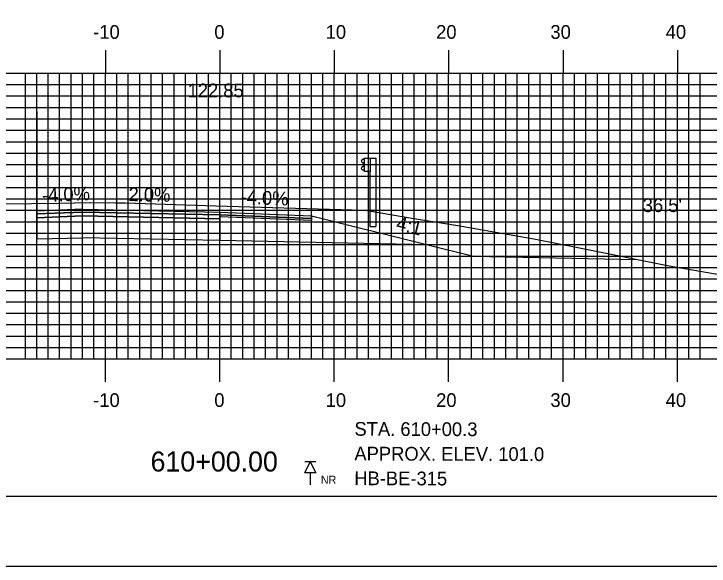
# Model space of a CAD drawing. Extents: x 843356 to 843699, y 363538 to 363758.
# Drawn here: x 843503.4 to 843564.2, y 363537.6 to 363585.9 of the extents above; entities that cross this region are included whole.
import ezdxf

# ---------------------------------------------------------------- set-up
doc = ezdxf.new("R2010")
doc.units = 0
for name, color, linetype in [('ANNOTATION', 7, 'Continuous'), ('BORDER', 7, 'Continuous'), ('BORING - NO REFUSAL', 7, 'Continuous'), ('D_Roadway_Centerline_Text', 7, 'Continuous'), ('D_Roadway_Edge_Shoulder', 7, 'Continuous'), ('D_Roadway_Edge_TW', 7, 'Continuous'), ('D_Roadway_FinishedGrade', 7, 'Continuous'), ('D_Roadway_Pavement', 7, 'Continuous'), ('D_Roadway_SubGrade', 7, 'Continuous'), ('D_Text_Standard', 7, 'Continuous'), ('H_V ANNOTATION', 7, 'Continuous'), ('M_Guardrail', 7, 'Continuous'), ('M_Roadway_Centerline', 7, 'Continuous'), ('MAJOR', 7, 'Continuous'), ('MINOR', 7, 'Continuous'), ('PLOT BOUNDARY', 7, 'Continuous'), ('S_Roadway_Centerline', 7, 'Continuous')]:
    doc.layers.add(name, color=color, linetype=linetype)

msp = doc.modelspace()

# ---------------------------------------------------------------- linework, layer by layer
at = {"layer": 'BORDER'}
msp.add_lwpolyline([(843371.824, 363543.721), (843691.824, 363543.721), (843691.824, 363753.721), (843371.824, 363753.721)], close=True, dxfattribs=at)
at = {"layer": 'BORING - NO REFUSAL'}
for p, q in [((843529.804, 363546.721), (843528.844, 363546.721)), ((843529.324, 363545.761), (843529.324, 363544.702))]:
    msp.add_line(p, q, dxfattribs=at)
msp.add_lwpolyline([(843529.324, 363546.721), (843529.804, 363545.761), (843528.844, 363545.761)], close=True, dxfattribs=at)
at = {"layer": 'D_Roadway_Edge_Shoulder'}
for points in [[(843509.424, 363568.812), (843505.424, 363568.652), (843505.424, 363568.402), (843509.424, 363568.562)], [(843521.424, 363568.572), (843529.424, 363568.252), (843529.424, 363568.002), (843521.424, 363568.322)]]:
    msp.add_lwpolyline(points, close=True, dxfattribs=at)
at = {"layer": 'D_Roadway_Edge_TW'}
msp.add_lwpolyline([(843509.424, 363568.812), (843521.424, 363568.572), (843521.424, 363568.322), (843509.424, 363568.562)], close=True, dxfattribs=at)
at = {"layer": 'D_Roadway_FinishedGrade'}
msp.add_lwpolyline([(843539.598, 363565.708), (843543.598, 363564.708), (843557.907, 363564.422)], dxfattribs=at)
at = {"layer": 'D_Roadway_Pavement'}
for points in [[(843509.424, 363568.562), (843505.424, 363568.402), (843505.424, 363568.068), (843509.424, 363568.228)], [(843509.424, 363568.562), (843521.424, 363568.322), (843521.424, 363567.988), (843509.424, 363568.228)], [(843521.424, 363568.322), (843529.424, 363568.002), (843529.424, 363567.835), (843521.424, 363568.155)]]:
    msp.add_lwpolyline(points, close=True, dxfattribs=at)
msp.add_lwpolyline([(843521.424, 363568.322), (843521.424, 363567.988)], dxfattribs=at)
msp.add_lwpolyline([(843521.424, 363568.322), (843521.424, 363567.988)], dxfattribs=at)
at = {"layer": 'D_Roadway_SubGrade'}
msp.add_line((843505.424, 363577.329), (843505.424, 363566.232), dxfattribs=at)
for points in [[(843509.424, 363568.228), (843505.424, 363568.068), (843505.424, 363568.402), (843505.424, 363568.652), (843505.424, 363566.232), (843509.424, 363566.312)], [(843509.424, 363568.228), (843521.424, 363567.988), (843521.424, 363566.072), (843509.424, 363566.312)], [(843521.424, 363567.988), (843521.424, 363568.322), (843529.424, 363568.002), (843529.424, 363568.252), (843539.598, 363565.708), (843521.424, 363566.072)]]:
    msp.add_lwpolyline(points, close=True, dxfattribs=at)
at = {"layer": 'M_Guardrail'}
for p, q in [((843534.069, 363573.291), (843534.559, 363573.291)), ((843534.069, 363572.125), (843534.069, 363573.291)), ((843534.559, 363573.291), (843535.05, 363573.291)), ((843534.559, 363573.291), (843534.559, 363572.125)), ((843535.05, 363573.291), (843535.05, 363567.291)), ((843533.971, 363573.197), (843533.827, 363573.097)), ((843533.827, 363572.954), (843534.022, 363572.818)), ((843534.069, 363573.218), (843533.987, 363573.204)), ((843534.056, 363572.753), (843534.056, 363572.662)), ((843534.022, 363572.598), (843533.827, 363572.462)), ((843533.827, 363572.319), (843533.971, 363572.219)), ((843533.987, 363572.212), (843534.069, 363572.197)), ((843534.559, 363572.125), (843534.069, 363572.125)), ((843534.559, 363567.291), (843534.559, 363572.125)), ((843534.559, 363567.291), (843535.05, 363567.291))]:
    msp.add_line(p, q, dxfattribs=at)
for centre, major_axis, start_param, end_param in [((843533.877, 363573.025), (-0.0877, 0), 5.323254, 7.243116), ((843533.994, 363573.163), (-0.0417, 0), 4.886922, 5.323254), ((843533.977, 363572.753), (0.0789, 0), 0, 0.959931), ((843533.977, 363572.662), (0.0789, 0), 5.323254, 6.283185), ((843533.877, 363572.39), (-0.0877, 0), 5.323254, 7.243116), ((843533.994, 363572.253), (-0.0417, 0), 0.959931, 1.396263)]:
    msp.add_ellipse(centre, major_axis=major_axis, ratio=0.995501, start_param=start_param, end_param=end_param, dxfattribs=at)
at = {"layer": 'MAJOR'}
for p, q in [((843511.424, 363582.725), (843511.424, 363580.721)), ((843521.424, 363582.725), (843521.424, 363580.721)), ((843531.424, 363582.725), (843531.424, 363580.721)), ((843541.424, 363582.725), (843541.424, 363580.721)), ((843551.424, 363582.725), (843551.424, 363580.721)), ((843561.424, 363582.725), (843561.424, 363580.721)), ((843381.424, 363580.721), (843661.424, 363580.721)), ((843381.424, 363580.721), (843661.424, 363580.721)), ((843511.424, 363555.721), (843511.424, 363580.721)), ((843521.424, 363555.721), (843521.424, 363580.721)), ((843531.424, 363555.721), (843531.424, 363580.721)), ((843541.424, 363555.721), (843541.424, 363580.721)), ((843551.424, 363555.721), (843551.424, 363580.721)), ((843561.424, 363555.721), (843561.424, 363580.721)), ((843381.424, 363575.721), (843661.424, 363575.721)), ((843381.424, 363570.721), (843661.424, 363570.721)), ((843381.424, 363565.721), (843661.424, 363565.721)), ((843381.424, 363560.721), (843661.424, 363560.721)), ((843381.424, 363555.721), (843661.424, 363555.721)), ((843381.424, 363555.721), (843661.424, 363555.721)), ((843511.424, 363553.717), (843511.424, 363555.721)), ((843521.424, 363553.717), (843521.424, 363555.721)), ((843531.424, 363553.717), (843531.424, 363555.721)), ((843541.424, 363553.717), (843541.424, 363555.721)), ((843551.424, 363553.717), (843551.424, 363555.721)), ((843561.424, 363553.717), (843561.424, 363555.721))]:
    msp.add_line(p, q, dxfattribs=at)
at = {"layer": 'MINOR'}
for p, q in [((843504.424, 363555.721), (843504.424, 363580.721)), ((843505.424, 363555.721), (843505.424, 363580.721)), ((843506.424, 363555.721), (843506.424, 363580.721)), ((843507.424, 363555.721), (843507.424, 363580.721)), ((843508.424, 363555.721), (843508.424, 363580.721)), ((843509.424, 363555.721), (843509.424, 363580.721)), ((843510.424, 363555.721), (843510.424, 363580.721)), ((843512.424, 363555.721), (843512.424, 363580.721)), ((843513.424, 363555.721), (843513.424, 363580.721)), ((843514.424, 363555.721), (843514.424, 363580.721)), ((843515.424, 363555.721), (843515.424, 363580.721)), ((843516.424, 363555.721), (843516.424, 363580.721)), ((843517.424, 363555.721), (843517.424, 363580.721)), ((843518.424, 363555.721), (843518.424, 363580.721)), ((843519.424, 363555.721), (843519.424, 363580.721)), ((843520.424, 363555.721), (843520.424, 363580.721)), ((843522.424, 363555.721), (843522.424, 363580.721)), ((843523.424, 363555.721), (843523.424, 363580.721)), ((843524.424, 363555.721), (843524.424, 363580.721)), ((843525.424, 363555.721), (843525.424, 363580.721)), ((843526.424, 363555.721), (843526.424, 363580.721)), ((843527.424, 363555.721), (843527.424, 363580.721)), ((843528.424, 363555.721), (843528.424, 363580.721)), ((843529.424, 363555.721), (843529.424, 363580.721)), ((843530.424, 363555.721), (843530.424, 363580.721)), ((843532.424, 363555.721), (843532.424, 363580.721)), ((843533.424, 363555.721), (843533.424, 363580.721)), ((843534.424, 363555.721), (843534.424, 363580.721)), ((843535.424, 363555.721), (843535.424, 363580.721)), ((843536.424, 363555.721), (843536.424, 363580.721)), ((843537.424, 363555.721), (843537.424, 363580.721)), ((843538.424, 363555.721), (843538.424, 363580.721)), ((843539.424, 363555.721), (843539.424, 363580.721)), ((843540.424, 363555.721), (843540.424, 363580.721)), ((843542.424, 363555.721), (843542.424, 363580.721)), ((843543.424, 363555.721), (843543.424, 363580.721)), ((843544.424, 363555.721), (843544.424, 363580.721)), ((843545.424, 363555.721), (843545.424, 363580.721)), ((843546.424, 363555.721), (843546.424, 363580.721)), ((843547.424, 363555.721), (843547.424, 363580.721)), ((843548.424, 363555.721), (843548.424, 363580.721)), ((843549.424, 363555.721), (843549.424, 363580.721)), ((843550.424, 363555.721), (843550.424, 363580.721)), ((843552.424, 363555.721), (843552.424, 363580.721)), ((843553.424, 363555.721), (843553.424, 363580.721)), ((843554.424, 363555.721), (843554.424, 363580.721)), ((843555.424, 363555.721), (843555.424, 363580.721)), ((843556.424, 363555.721), (843556.424, 363580.721)), ((843557.424, 363555.721), (843557.424, 363580.721)), ((843558.424, 363555.721), (843558.424, 363580.721)), ((843559.424, 363555.721), (843559.424, 363580.721)), ((843560.424, 363555.721), (843560.424, 363580.721)), ((843562.424, 363555.721), (843562.424, 363580.721)), ((843563.424, 363555.721), (843563.424, 363580.721)), ((843381.424, 363579.721), (843661.424, 363579.721)), ((843381.424, 363578.721), (843661.424, 363578.721)), ((843381.424, 363577.721), (843661.424, 363577.721)), ((843381.424, 363576.721), (843661.424, 363576.721)), ((843381.424, 363574.721), (843661.424, 363574.721)), ((843381.424, 363573.721), (843661.424, 363573.721)), ((843381.424, 363572.721), (843661.424, 363572.721)), ((843381.424, 363571.721), (843661.424, 363571.721)), ((843381.424, 363569.721), (843661.424, 363569.721)), ((843381.424, 363568.721), (843661.424, 363568.721)), ((843381.424, 363567.721), (843661.424, 363567.721)), ((843381.424, 363566.721), (843661.424, 363566.721)), ((843381.424, 363564.721), (843661.424, 363564.721)), ((843381.424, 363563.721), (843661.424, 363563.721)), ((843381.424, 363562.721), (843661.424, 363562.721)), ((843381.424, 363561.721), (843661.424, 363561.721)), ((843381.424, 363559.721), (843661.424, 363559.721)), ((843381.424, 363558.721), (843661.424, 363558.721)), ((843381.424, 363557.721), (843661.424, 363557.721)), ((843381.424, 363556.721), (843661.424, 363556.721))]:
    msp.add_line(p, q, dxfattribs=at)
at = {"layer": 'PLOT BOUNDARY'}
msp.add_lwpolyline([(843355.638, 363537.603), (843695.638, 363537.603), (843695.638, 363757.603), (843355.638, 363757.603)], close=True, dxfattribs=at)
at = {"layer": 'S_Roadway_Centerline'}
msp.add_lwpolyline([(843500.121, 363569.26), (843507.382, 363569.351), (843510.071, 363569.407), (843512.294, 363569.376), (843513.155, 363569.367), (843521.066, 363569.12), (843532.991, 363568.776), (843534.059, 363568.732), (843534.639, 363568.656), (843538.204, 363568.023), (843542.218, 363567.397), (843548.874, 363566.238), (843552.851, 363565.447), (843560.709, 363563.854), (843572.188, 363561.879), (843573.125, 363561.724), (843576.365, 363561.239), (843585.567, 363564.955), (843594.124, 363568.35), (843602.151, 363571.244)], dxfattribs=at)

# ---------------------------------------------------------------- texts
at = {"layer": 'ANNOTATION'}
for s, rotation, p in [('-4.0%', 2.29061, (843505.9, 363569.439)), ('2.0%', 358.85424, (843513.431, 363569.532)), ('-4.0%', 357.70939, (843523.216, 363569.302)), ('4:1', 345.96376, (843536.757, 363567.054))]:
    msp.add_text(s, height=1.2, rotation=rotation, dxfattribs=at).set_placement(p)
at = {"layer": 'BORING - NO REFUSAL'}
for s, p in [('STA. 610+00.3', (843533.192, 363549.005)), ('APPROX. ELEV. 101.0', (843533.185, 363546.845)), ('HB-BE-315', (843533.178, 363544.685))]:
    msp.add_text(s, height=1.2, rotation=359.81416, dxfattribs=at).set_placement(p)
msp.add_text('NR', height=0.6998, dxfattribs=at).set_placement((843530.257, 363544.806))
at = {"layer": 'D_Roadway_Centerline_Text'}
msp.add_text('122.85', height=1.2, dxfattribs=at).set_placement((843518.604, 363578.602))
at = {"layer": 'D_Text_Standard'}
msp.add_text("36.5'", height=1.2, dxfattribs=at).set_placement((843558.39, 363568.569))
at = {"layer": 'H_V ANNOTATION'}
for s, height, p in [('-10', 1.2, (843510.354, 363583.721)), ('0', 1.2, (843520.942, 363583.721)), ('10', 1.2, (843530.675, 363583.721)), ('20', 1.2, (843540.332, 363583.721)), ('30', 1.2, (843550.322, 363583.721)), ('40', 1.2, (843560.397, 363583.721)), ('-10', 1.2, (843510.354, 363551.521)), ('0', 1.2, (843520.942, 363551.521)), ('10', 1.2, (843530.675, 363551.521)), ('20', 1.2, (843540.332, 363551.521)), ('30', 1.2, (843550.322, 363551.521)), ('40', 1.2, (843560.397, 363551.521)), ('610+00.00', 1.75, (843515.369, 363545.877))]:
    msp.add_text(s, height=height, dxfattribs=at).set_placement(p)
at = {"layer": 'M_Roadway_Centerline'}
for s, p in [('C', (843510.065, 363569.407)), ('L', (843510.071, 363569.4))]:
    msp.add_text(s, height=0.0146, dxfattribs=at).set_placement(p)

doc.saveas('drawing.dxf')
